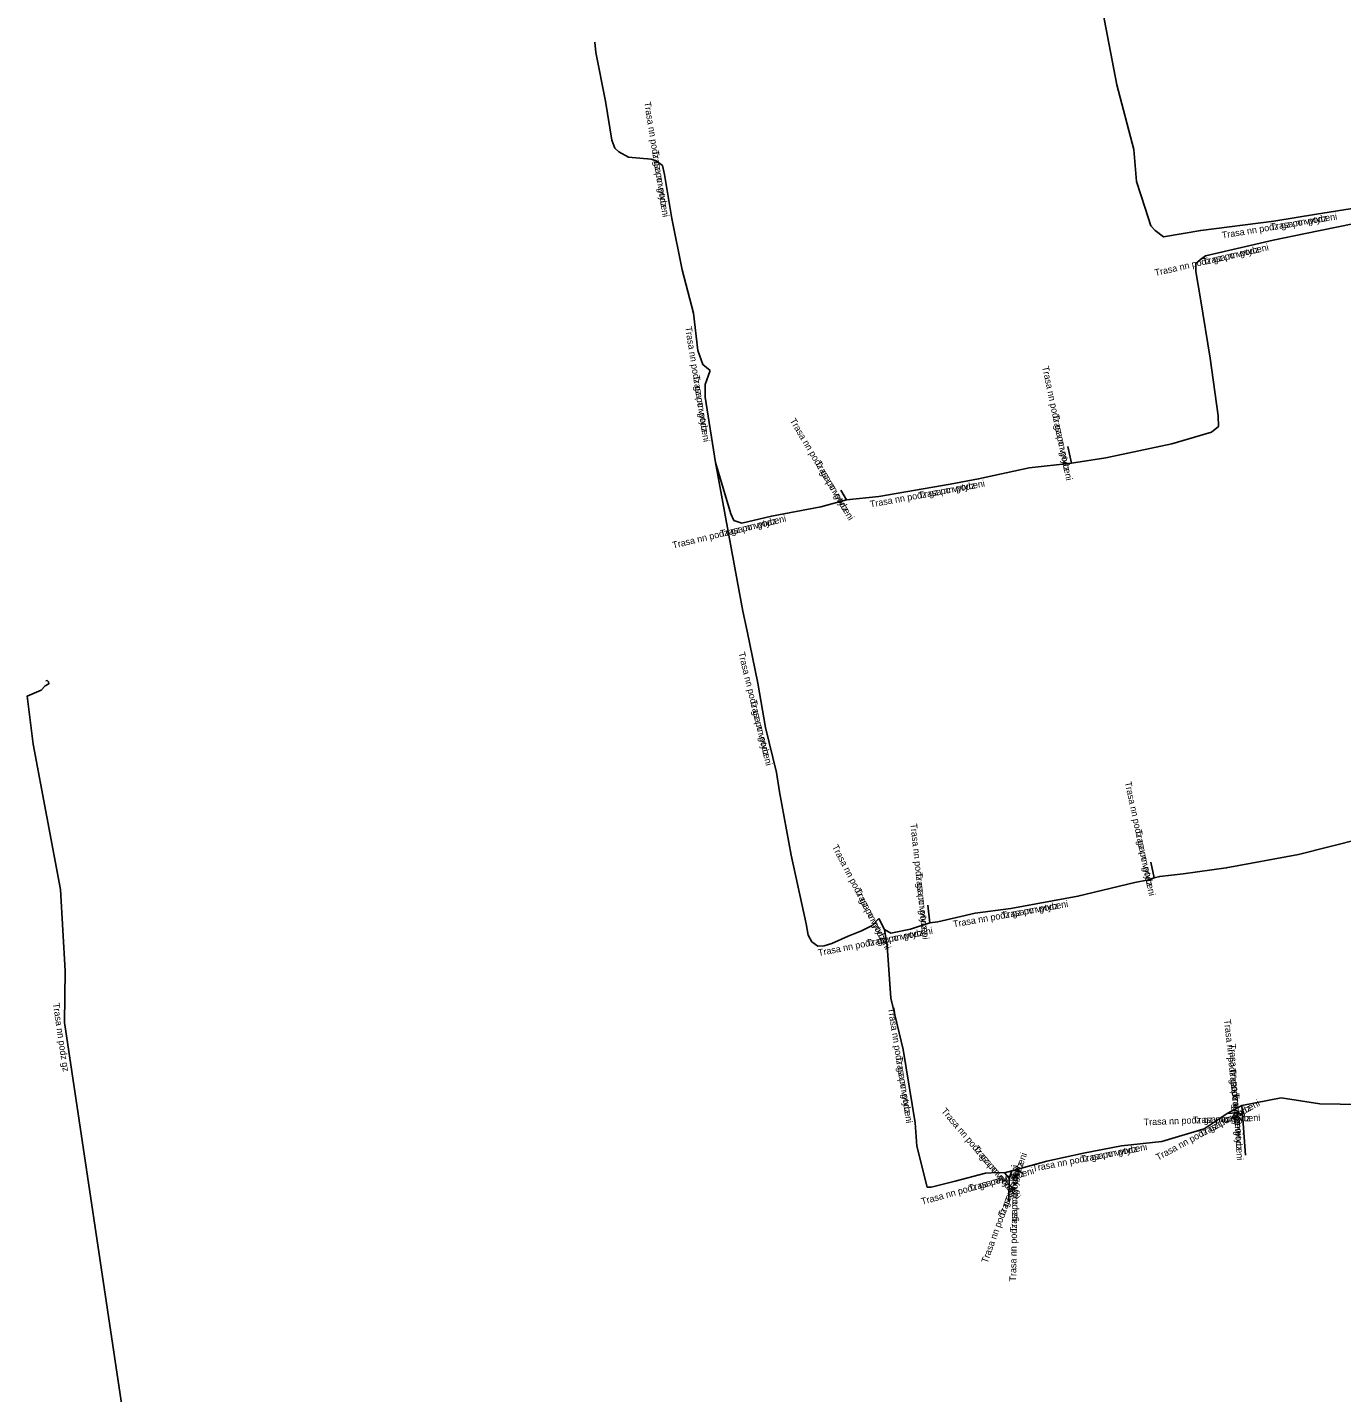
# Model space of a CAD drawing. Extents: x -876384 to -875659, y -1020218 to -1019588.
# Drawn here: x -876127.1 to -876029.1, y -1020036.5 to -1019934.7 of the extents above; entities that cross this region are included whole.
import ezdxf

# ---------------------------------------------------------------- set-up
doc = ezdxf.new("R2010")
doc.units = 0
doc.layers.add('Popiskový text - Ostatní atributy Trasy', color=7, linetype='Continuous')
doc.layers.add('Spojnice NN', color=7, linetype='Continuous')

msp = doc.modelspace()

# ---------------------------------------------------------------- linework, layer by layer
at = {"layer": 'Spojnice NN'}
for points in [[(-876046.32, -1019930.37), (-876047.08, -1019930.93), (-876047.26, -1019931.59), (-876046.92, -1019933.56), (-876045.88, -1019938.99), (-876044.61, -1019943.83), (-876044.42, -1019946.2), (-876043.76, -1019948.18), (-876043.34, -1019949.51), (-876043.03, -1019949.85), (-876042.41, -1019950.34), (-876039.62, -1019949.85), (-876034.17, -1019949.16), (-876030.99, -1019948.63), (-876028.02, -1019948.16), (-876024.37, -1019947.45), (-876019.01, -1019946.41), (-876015.26, -1019945.54), (-876012.33, -1019944.94), (-876009.41, -1019944.24), (-876005.45, -1019943.4), (-876003.75, -1019943.35), (-875999.53, -1019943.84)], [(-876046.32, -1019930.37), (-876047.08, -1019930.93), (-876047.26, -1019931.59), (-876046.92, -1019933.56), (-876045.88, -1019938.99), (-876044.61, -1019943.83), (-876044.42, -1019946.2), (-876043.76, -1019948.18), (-876043.34, -1019949.51), (-876043.03, -1019949.85), (-876042.41, -1019950.34), (-876039.62, -1019949.85), (-876034.17, -1019949.16), (-876030.99, -1019948.63), (-876028.02, -1019948.16), (-876024.37, -1019947.45), (-876019.01, -1019946.41), (-876015.26, -1019945.54), (-876012.33, -1019944.94), (-876009.41, -1019944.24), (-876005.45, -1019943.4), (-876003.75, -1019943.35), (-875999.53, -1019943.84)], [(-876076.2, -1019960.3), (-876076.74, -1019959.85), (-876077.11, -1019958.81), (-876077.43, -1019956.03), (-876078.29, -1019952.8), (-876079.06, -1019948.96), (-876079.59, -1019945.69), (-876079.75, -1019945.02), (-876080.22, -1019944.67), (-876080.59, -1019944.55), (-876082.28, -1019944.39), (-876083, -1019944), (-876083.29, -1019943.72), (-876083.53, -1019943.13), (-876084, -1019940.22), (-876084.72, -1019936.58), (-876084.8, -1019935.82)], [(-876076.2, -1019960.3), (-876076.74, -1019959.85), (-876077.11, -1019958.81), (-876077.43, -1019956.03), (-876078.29, -1019952.8), (-876079.06, -1019948.96), (-876079.59, -1019945.69), (-876079.75, -1019945.02), (-876080.22, -1019944.67), (-876080.59, -1019944.55), (-876082.28, -1019944.39), (-876083, -1019944), (-876083.29, -1019943.72), (-876083.53, -1019943.13), (-876084, -1019940.22), (-876084.72, -1019936.58), (-876084.8, -1019935.82)], [(-876009.91, -1019946.97), (-876010.39, -1019946.23), (-876010.86, -1019946.25), (-876011.96, -1019946.62), (-876015.42, -1019947.19), (-876018.66, -1019947.82), (-876024.27, -1019948.6), (-876028.29, -1019949.37), (-876031.81, -1019950.07), (-876034.22, -1019950.58), (-876039.28, -1019951.74), (-876039.64, -1019952.03), (-876040, -1019952.31), (-876040, -1019952.91), (-876039.65, -1019954.95), (-876038.91, -1019959.38), (-876038.32, -1019963.68), (-876038.31, -1019964.47), (-876038.83, -1019964.88), (-876041.77, -1019965.75), (-876046.71, -1019966.8), (-876049.27, -1019967.19)], [(-876009.91, -1019946.97), (-876010.39, -1019946.23), (-876010.86, -1019946.25), (-876011.96, -1019946.62), (-876015.42, -1019947.19), (-876018.66, -1019947.82), (-876024.27, -1019948.6), (-876028.29, -1019949.37), (-876031.81, -1019950.07), (-876034.22, -1019950.58), (-876039.28, -1019951.74), (-876039.64, -1019952.03), (-876040, -1019952.31), (-876040, -1019952.91), (-876039.65, -1019954.95), (-876038.91, -1019959.38), (-876038.32, -1019963.68), (-876038.31, -1019964.47), (-876038.83, -1019964.88), (-876041.77, -1019965.75), (-876046.71, -1019966.8), (-876049.27, -1019967.19)], [(-876076.2, -1019960.3), (-876076.57, -1019961.34), (-876076.57, -1019962.29), (-876075.8, -1019967.15)], [(-876076.2, -1019960.3), (-876076.57, -1019961.34), (-876076.57, -1019962.29), (-876075.8, -1019967.15)], [(-876049.27, -1019967.19), (-876049.53, -1019965.96)], [(-876049.27, -1019967.19), (-876049.53, -1019965.96)], [(-876075.8, -1019967.15), (-876075.08, -1019971.08), (-876074.17, -1019975.95), (-876073.76, -1019978.24), (-876073.44, -1019979.73), (-876072.65, -1019983.59), (-876072.07, -1019986.9), (-876071.25, -1019990.25), (-876071.03, -1019991.71), (-876070.16, -1019996.41), (-876069.05, -1020001.55), (-876068.89, -1020002.39), (-876068.61, -1020002.87), (-876068.17, -1020003.21), (-876067.7, -1020003.17), (-876067.12, -1020003.01), (-876065.9, -1020002.45), (-876064.92, -1020002.06), (-876064.12, -1020001.66), (-876063.62, -1020001.15)], [(-876075.8, -1019967.15), (-876074.66, -1019970.97), (-876074.43, -1019971.47), (-876073.84, -1019971.68), (-876071.63, -1019971.15), (-876067.95, -1019970.45), (-876066.03, -1019969.93)], [(-876075.8, -1019967.15), (-876075.08, -1019971.08), (-876074.17, -1019975.95), (-876073.76, -1019978.24), (-876073.44, -1019979.73), (-876072.65, -1019983.59), (-876072.07, -1019986.9), (-876071.25, -1019990.25), (-876071.03, -1019991.71), (-876070.16, -1019996.41), (-876069.05, -1020001.55), (-876068.89, -1020002.39), (-876068.61, -1020002.87), (-876068.17, -1020003.21), (-876067.7, -1020003.17), (-876067.12, -1020003.01), (-876065.9, -1020002.45), (-876064.92, -1020002.06), (-876064.12, -1020001.66), (-876063.62, -1020001.15)], [(-876075.8, -1019967.15), (-876074.66, -1019970.97), (-876074.43, -1019971.47), (-876073.84, -1019971.68), (-876071.63, -1019971.15), (-876067.95, -1019970.45), (-876066.03, -1019969.93)], [(-876066.03, -1019969.93), (-876063.62, -1019969.68), (-876058.3, -1019968.76), (-876056.18, -1019968.37), (-876052.41, -1019967.54), (-876049.27, -1019967.19)], [(-876066.03, -1019969.93), (-876063.62, -1019969.68), (-876058.3, -1019968.76), (-876056.18, -1019968.37), (-876052.41, -1019967.54), (-876049.27, -1019967.19)], [(-876066.03, -1019969.93), (-876066.45, -1019969.22)], [(-876066.03, -1019969.93), (-876066.45, -1019969.22)], [(-876043.1, -1019998.12), (-876042.68, -1019998.01), (-876040.94, -1019997.81), (-876037.72, -1019997.37), (-876032.34, -1019996.37), (-876027.71, -1019995.21), (-876021.96, -1019994.19), (-876017.47, -1019993.38), (-876013.69, -1019992.69), (-876009.04, -1019991.79), (-876002.9, -1019991.16), (-876002.17, -1019990.97), (-876001.82, -1019990.74), (-876001.65, -1019990.42), (-876001.69, -1019988.63), (-876001.9, -1019985.73), (-876002.68, -1019980.94), (-876003.52, -1019976.94), (-876003.88, -1019976.49), (-876004.36, -1019976.15), (-876004.68, -1019975.87)], [(-876043.1, -1019998.12), (-876042.68, -1019998.01), (-876040.94, -1019997.81), (-876037.72, -1019997.37), (-876032.34, -1019996.37), (-876027.71, -1019995.21), (-876021.96, -1019994.19), (-876017.47, -1019993.38), (-876013.69, -1019992.69), (-876009.04, -1019991.79), (-876002.9, -1019991.16), (-876002.17, -1019990.97), (-876001.82, -1019990.74), (-876001.65, -1019990.42), (-876001.69, -1019988.63), (-876001.9, -1019985.73), (-876002.68, -1019980.94), (-876003.52, -1019976.94), (-876003.88, -1019976.49), (-876004.36, -1019976.15), (-876004.68, -1019975.87)], [(-876125.72, -1019983.42), (-876125.61, -1019983.41), (-876125.53, -1019983.5), (-876125.5, -1019983.66), (-876125.78, -1019983.81), (-876126.07, -1019984.11), (-876127.1, -1019984.56), (-876126.66, -1019988.15), (-876124.62, -1019998.97), (-876124.27, -1020005.04), (-876124.33, -1020008.89), (-876120.04, -1020037.62), (-876119.65, -1020039.4), (-876119.5, -1020040.08)], [(-876043.35, -1019996.95), (-876043.1, -1019998.12)], [(-876043.35, -1019996.95), (-876043.1, -1019998.12)], [(-876059.83, -1020001.47), (-876059.23, -1020001.4), (-876056.45, -1020000.74), (-876053.79, -1020000.39), (-876048.78, -1019999.49), (-876044.53, -1019998.47), (-876043.51, -1019998.26), (-876043.1, -1019998.12)], [(-876059.83, -1020001.47), (-876059.23, -1020001.4), (-876056.45, -1020000.74), (-876053.79, -1020000.39), (-876048.78, -1019999.49), (-876044.53, -1019998.47), (-876043.51, -1019998.26), (-876043.1, -1019998.12)], [(-876059.97, -1020000.15), (-876059.83, -1020001.47)], [(-876059.97, -1020000.15), (-876059.83, -1020001.47)], [(-876063.2, -1020001.96), (-876063.62, -1020001.15)], [(-876063.2, -1020001.96), (-876063.62, -1020001.15)], [(-876059.83, -1020001.47), (-876061.25, -1020001.94), (-876062.72, -1020002.23), (-876063.2, -1020001.96)], [(-876059.83, -1020001.47), (-876061.25, -1020001.94), (-876062.72, -1020002.23), (-876063.2, -1020001.96)], [(-876054.25, -1020020.11), (-876054.81, -1020020.08), (-876055.68, -1020020.13), (-876057.93, -1020020.73), (-876059.73, -1020021.16), (-876060.03, -1020021.16), (-876060.8, -1020018.11), (-876060.92, -1020016.38), (-876061.8, -1020010.9), (-876062.72, -1020007.08), (-876062.99, -1020003.18), (-876063.2, -1020001.96)], [(-876054.25, -1020020.11), (-876054.81, -1020020.08), (-876055.68, -1020020.13), (-876057.93, -1020020.73), (-876059.73, -1020021.16), (-876060.03, -1020021.16), (-876060.8, -1020018.11), (-876060.92, -1020016.38), (-876061.8, -1020010.9), (-876062.72, -1020007.08), (-876062.99, -1020003.18), (-876063.2, -1020001.96)], [(-876036.57, -1020015.08), (-876033.62, -1020014.51), (-876030.75, -1020014.95), (-876026.19, -1020015.03), (-876021.67, -1020014.65), (-876019.83, -1020013.55), (-876016.85, -1020012.7), (-876013.43, -1020011.88), (-876009.66, -1020010.77), (-876007.97, -1020010.49)], [(-876036.57, -1020015.08), (-876033.62, -1020014.51), (-876030.75, -1020014.95), (-876026.19, -1020015.03), (-876021.67, -1020014.65), (-876019.83, -1020013.55), (-876016.85, -1020012.7), (-876013.43, -1020011.88), (-876009.66, -1020010.77), (-876007.97, -1020010.49)], [(-876037.66, -1020015.67), (-876036.57, -1020015.08)], [(-876037.66, -1020015.67), (-876036.57, -1020015.08)], [(-876036.57, -1020015.08), (-876036.5, -1020015.76)], [(-876036.57, -1020015.08), (-876036.5, -1020015.76)], [(-876053.71, -1020019.96), (-876051.09, -1020019.23), (-876048.36, -1020018.64), (-876045.53, -1020018.1), (-876042.52, -1020017.77), (-876039.38, -1020016.82), (-876037.66, -1020015.67)], [(-876053.71, -1020019.96), (-876051.09, -1020019.23), (-876048.36, -1020018.64), (-876045.53, -1020018.1), (-876042.52, -1020017.77), (-876039.38, -1020016.82), (-876037.66, -1020015.67)], [(-876037.66, -1020015.67), (-876036.9, -1020015.64), (-876036.5, -1020015.76)], [(-876037.66, -1020015.67), (-876036.9, -1020015.64), (-876036.5, -1020015.76)], [(-876036.5, -1020015.76), (-876036.29, -1020018.79)], [(-876036.5, -1020015.76), (-876036.29, -1020018.79)], [(-876053.71, -1020019.96), (-876054.25, -1020020.11)], [(-876053.71, -1020019.96), (-876054.25, -1020020.11)], [(-876054.25, -1020020.11), (-876053.91, -1020020.51)], [(-876054.25, -1020020.11), (-876053.91, -1020020.51)], [(-876053.91, -1020020.51), (-876053.71, -1020019.96)], [(-876053.91, -1020020.51), (-876053.71, -1020019.96)], [(-876053.94, -1020022.23), (-876053.91, -1020020.51)], [(-876053.94, -1020022.23), (-876053.91, -1020020.51)]]:
    msp.add_lwpolyline(points, dxfattribs=at)

# ---------------------------------------------------------------- texts
at = {"layer": 'Popiskový text - Ostatní atributy Trasy'}
for s, rotation, p in [('Trasa nn podz gz po vytyceni', 279.2064, (-876081.12, -1019940.3)), ('Trasa nn podz', 279.2064, (-876080.53, -1019943.94)), ('Trasa nn podz gz po vytyceni', 9.4623, (-876038.01, -1019950.46)), ('Trasa nn podz', 9.4623, (-876034.38, -1019949.85)), ('Trasa nn podz gz po vytyceni', 12.9119, (-876043, -1019953.26)), ('Trasa nn podz', 12.9119, (-876039.4, -1019952.44)), ('Trasa nn podz gz po vytyceni', 279.0029, (-876078.06, -1019957.06)), ('Trasa nn podz gz po vytyceni', 281.9356, (-876051.45, -1019960.02)), ('Trasa nn podz', 279.0029, (-876077.48, -1019960.7)), ('Trasa nn podz gz po vytyceni', 300.6064, (-876070.28, -1019964.03)), ('Trasa nn podz', 281.9356, (-876050.69, -1019963.63)), ('Trasa nn podz', 300.6064, (-876068.4, -1019967.2)), ('Trasa nn podz gz po vytyceni', 10.4237, (-876064.24, -1019970.51)), ('Trasa nn podz', 10.4237, (-876060.61, -1019969.85)), ('Trasa nn podz gz po vytyceni', 13.4859, (-876078.95, -1019973.57)), ('Trasa nn podz', 13.4859, (-876075.37, -1019972.71)), ('Trasa nn podz gz po vytyceni', 283.7542, (-876074.1, -1019981.34)), ('Trasa nn podz', 283.7542, (-876073.22, -1019984.92)), ('Trasa nn podz gz po vytyceni', 282.0613, (-876045.29, -1019990.99)), ('Trasa nn podz gz po vytyceni', 276.0542, (-876061.27, -1019994.08)), ('Trasa nn podz', 282.0613, (-876044.52, -1019994.59)), ('Trasa nn podz gz po vytyceni', 297.4076, (-876067.13, -1019995.79)), ('Trasa nn podz', 276.0542, (-876060.88, -1019997.75)), ('Trasa nn podz', 297.4076, (-876065.44, -1019999.06)), ('Trasa nn podz gz po vytyceni', 10.184, (-876058.04, -1020001.81)), ('Trasa nn podz', 10.184, (-876054.41, -1020001.16)), ('Trasa nn podz gz po vytyceni', 11.1599, (-876068.1, -1020003.95)), ('Trasa nn podz', 11.1599, (-876064.48, -1020003.24)), ('Trasa nn podz gz', 278.4927, (-876125.2, -1020007.48)), ('Trasa nn podz gz po vytyceni', 279.1229, (-876062.95, -1020007.84)), ('Trasa nn podz gz po vytyceni', 275.8774, (-876037.88, -1020008.69)), ('Trasa nn podz gz po vytyceni', 273.9647, (-876037.52, -1020010.5)), ('Trasa nn podz', 279.1229, (-876062.36, -1020011.48)), ('Trasa nn podz', 275.8774, (-876037.5, -1020012.36)), ('Trasa nn podz gz po vytyceni', 28.426, (-876042.81, -1020019.2)), ('Trasa nn podz', 28.426, (-876039.57, -1020017.45)), ('Trasa nn podz', 273.9647, (-876037.26, -1020014.18)), ('Trasa nn podz gz po vytyceni', 310.3645, (-876059, -1020015.52)), ('Trasa nn podz gz po vytyceni', 2.2605, (-876043.87, -1020016.57)), ('Trasa nn podz', 2.2605, (-876040.19, -1020016.42)), ('Trasa nn podz', 310.3645, (-876056.61, -1020018.33)), ('Trasa nn podz gz po vytyceni', 10.8029, (-876052.13, -1020020.02)), ('Trasa nn podz', 10.8029, (-876048.51, -1020019.33)), ('Trasa nn podz gz po vytyceni', 70.0169, (-876055.53, -1020026.88)), ('Trasa nn podz gz po vytyceni', 15.5241, (-876060.39, -1020022.49)), ('Trasa nn podz', 15.5241, (-876056.84, -1020021.5)), ('Trasa nn podz', 70.0169, (-876054.27, -1020023.42)), ('Trasa nn podz gz po vytyceni', 89.0008, (-876053.39, -1020028.21)), ('Trasa nn podz', 89.0008, (-876053.33, -1020024.53))]:
    msp.add_text(s, height=0.5, rotation=rotation, dxfattribs=at).set_placement(p)

doc.saveas('drawing.dxf')
